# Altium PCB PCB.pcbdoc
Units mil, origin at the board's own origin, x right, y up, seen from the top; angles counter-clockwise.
Board outline 2605 x 3135 mil, 2 copper layers (Top Layer, Bottom Layer); 0 components, 0 nets, 4 pads, 4 vias.
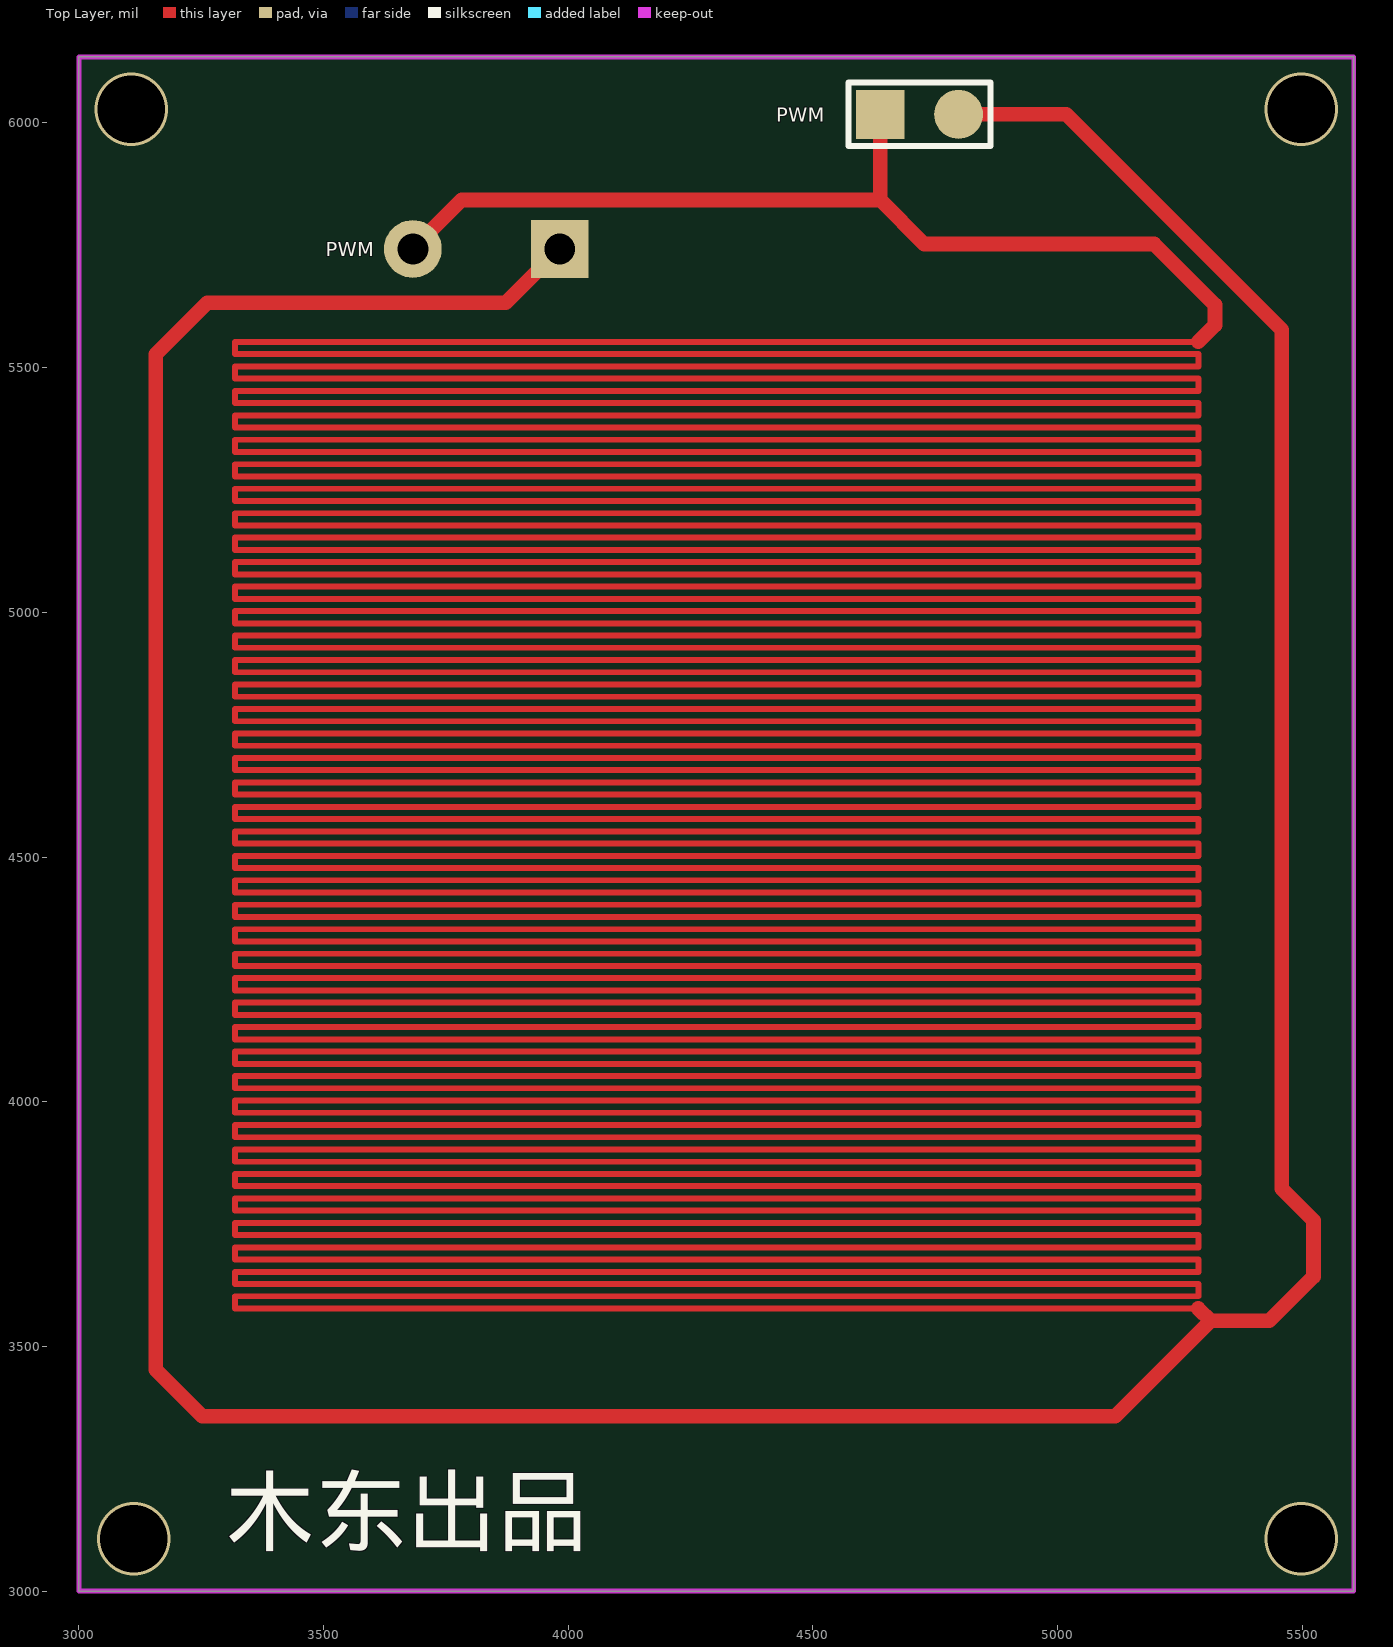
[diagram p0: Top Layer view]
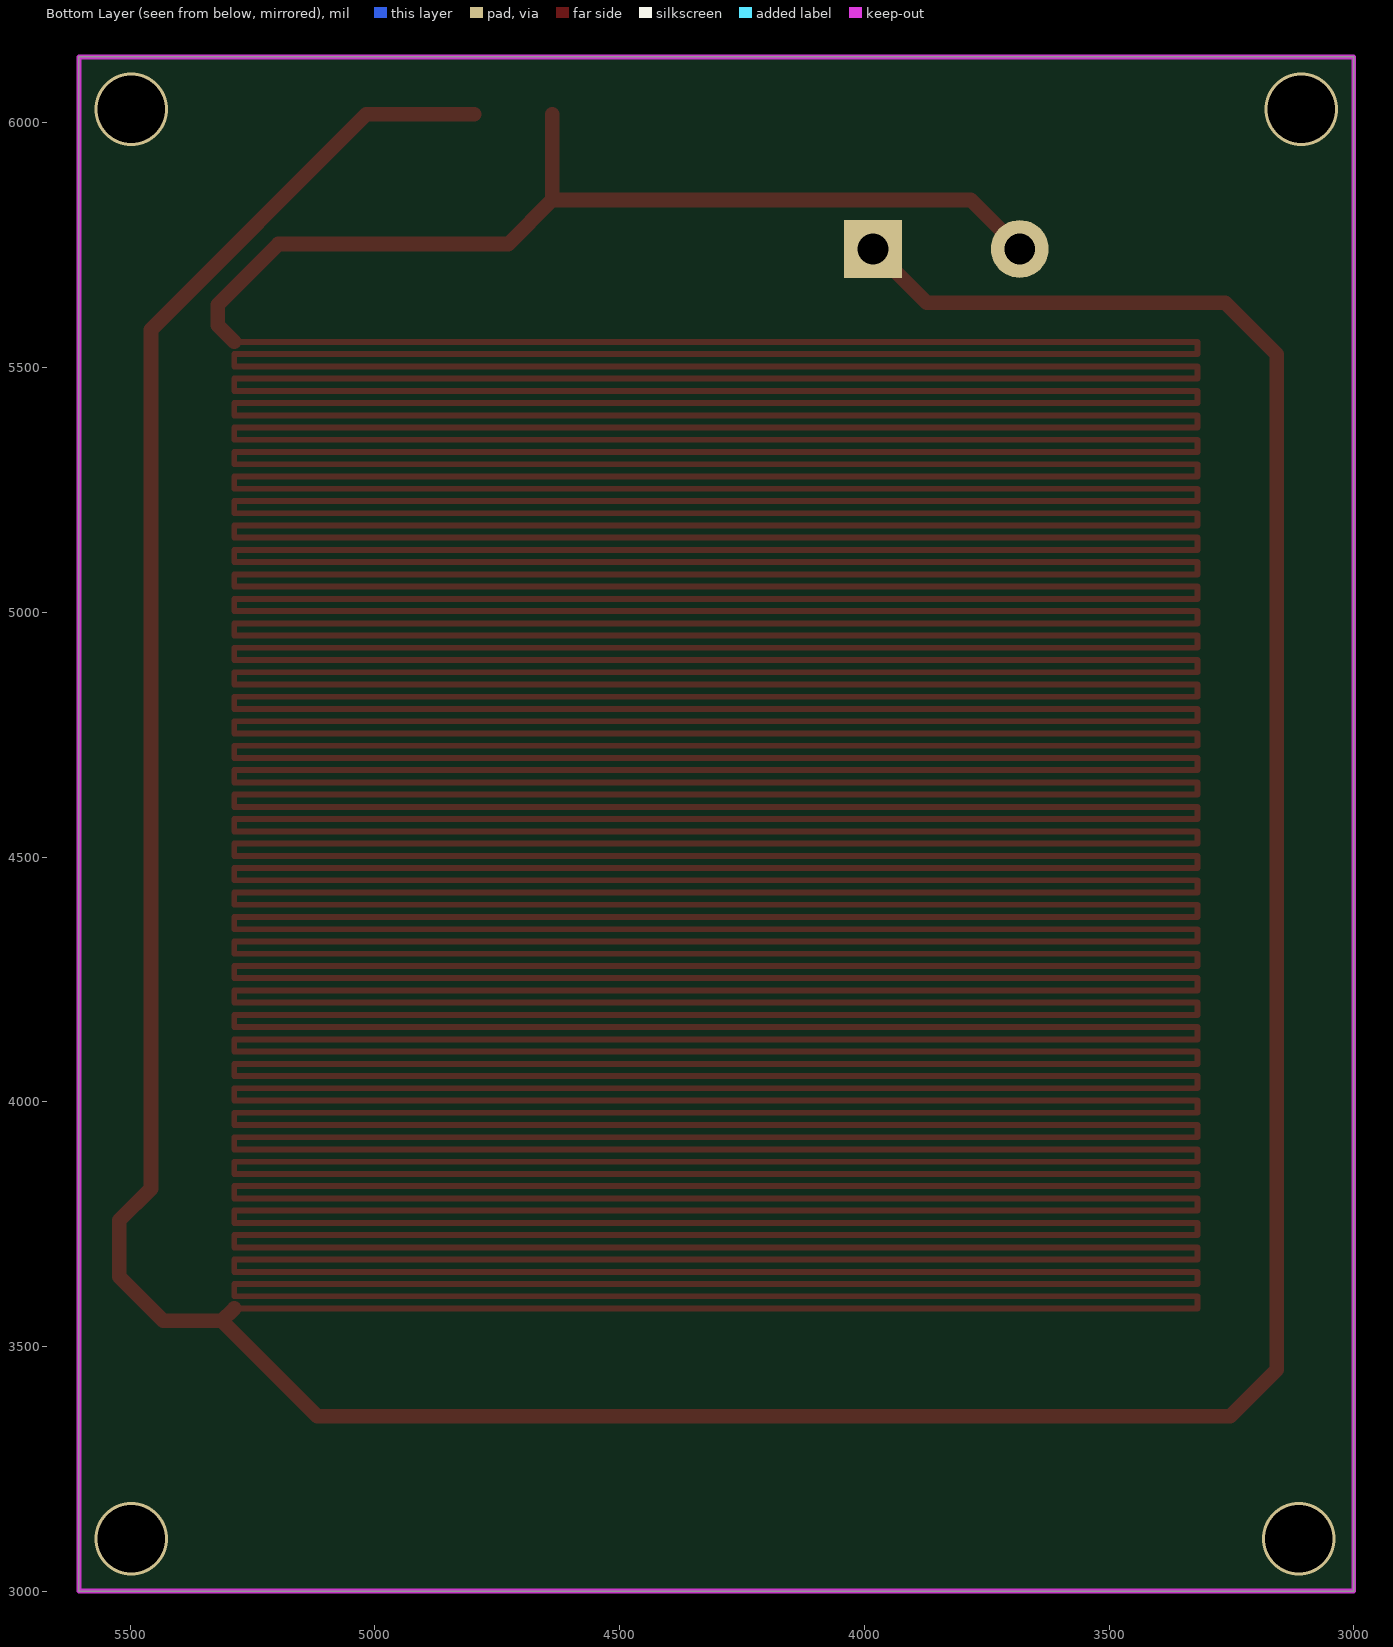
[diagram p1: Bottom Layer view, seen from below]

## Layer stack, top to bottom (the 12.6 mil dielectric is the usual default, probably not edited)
Top Layer: signal copper (thickness not stored)
Dielectric: dielectric 12.6, FR-4, Dk 4.8
Bottom Layer: signal copper (thickness not stored)

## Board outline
3000,3000 5605,3000 5605,6135 3000,6135

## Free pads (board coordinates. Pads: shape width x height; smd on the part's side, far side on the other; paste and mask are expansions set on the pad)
  rect 118.1x118.1 hole 63: GND(3982.5,5742.51)
  round 100 smd: GND(4797.5,6017.5)
  round 118.1 hole 63: PWM(3682.5,5742.5)
  rect 100x100 smd: PWM(4637.5,6017.5)

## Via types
v1: diameter 150, hole 137.8, Top Layer to Bottom Layer, 4 vias

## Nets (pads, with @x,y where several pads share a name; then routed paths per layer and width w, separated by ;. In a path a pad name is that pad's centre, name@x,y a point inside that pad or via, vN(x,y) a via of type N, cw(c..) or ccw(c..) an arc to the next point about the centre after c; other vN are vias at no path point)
copper on no net: | length 169840
  Top Layer w12: 5287.5,3577.5 3319,3577.5 3319,3602.5 5287.5,3602.5 5287.5,3627.5 3319,3627.5 3319,3652.5 5287.5,3652.5 5287.5,3677.5 3319,3677.5 3319,3702.5 5287.5,3702.5 5287.5,3727.5 3319,3727.5 3319,3752.5 5287.5,3752.5 5287.5,3777.5 3319,3777.5 3319,3802.5 5287.5,3802.5 5287.5,3827.5 3319,3827.5 3319,3852.5 5287.5,3852.5 5287.5,3877.5 3319,3877.5 3319,3902.5 5287.5,3902.5 5287.5,3927.5 3319,3927.5 3319,3952.5 5287.5,3952.5 5287.5,3977.5 3319,3977.5 3319,4002.5 5287.5,4002.5 5287.5,4027.5 3319,4027.5 3319,4052.5 5287.5,4052.5 5287.5,4077.5 3319,4077.5 3319,4102.5 5287.5,4102.5 5287.5,4127.5 3319,4127.5 3319,4152.5 5287.5,4152.5 5287.5,4177.5 3319,4177.5 3319,4202.5 5287.5,4202.5 5287.5,4227.5 3319,4227.5 3319,4252.5 5287.5,4252.5 5287.5,4277.5 3319,4277.5 3319,4302.5 5287.5,4302.5 5287.5,4327.5 3319,4327.5 3319,4352.5 5287.5,4352.5 5287.5,4377.5 3319,4377.5 3319,4402.5 5287.5,4402.5 5287.5,4427.5 3319,4427.5 3319,4452.5 5287.5,4452.5 5287.5,4477.5 3319,4477.5 3319,4502.5 5287.5,4502.5 5287.5,4527.5 3319,4527.5 3319,4552.5 5287.5,4552.5 5287.5,4577.5 3319,4577.5 3319,4602.5 5287.5,4602.5 5287.5,4627.5 3319,4627.5 3319,4652.5 5287.5,4652.5 5287.5,4677.5 3319,4677.5 3319,4702.5 5287.5,4702.5 5287.5,4727.5 3319,4727.5 3319,4752.5 5287.5,4752.5 5287.5,4777.5 3319,4777.5 3319,4802.5 5287.5,4802.5 5287.5,4827.5 3319,4827.5 3319,4852.5 5287.5,4852.5 5287.5,4877.5 3319,4877.5 3319,4902.5 5287.5,4902.5 5287.5,4927.5 3319,4927.5 3319,4952.5 5287.5,4952.5 5287.5,4977.5 3319,4977.5 3319,5002.5 5287.5,5002.5 5287.5,5027.5 3319,5027.5 3319,5052.5 5287.5,5052.5 5287.5,5077.5 3319,5077.5 3319,5102.5 5287.5,5102.5 5287.5,5127.5 3319,5127.5 3319,5152.5 5287.5,5152.5 5287.5,5177.5 3319,5177.5 3319,5202.5 5287.5,5202.5 5287.5,5227.5 3319,5227.5 3319,5252.5 5287.5,5252.5 5287.5,5277.5 3319,5277.5 3319,5302.5 5287.5,5302.5 5287.5,5327.5 3319,5327.5 3319,5352.5 5287.5,5352.5 5287.5,5377.5 3319,5377.5 3319,5402.5 5287.5,5402.5 5287.5,5427.5 3319,5427.5 3319,5452.5 5287.5,5452.5 5287.5,5477.5 3319,5477.5 3319,5502.5 5287.5,5502.5 5287.5,5527.5 3319,5527.5 3319,5552.5 5287.5,5552.5
  Top Layer w30: 3682.5,5742.5 3782.5,5842.5 4637.5,5842.5 ; 3982.5,5742.51 3872.49,5632.5 3262.5,5632.5 3157.5,5527.5 3157.5,3452.5 3252.5,3357.5 5117.5,3357.5 5312.5,3552.5 ; 4637.5,6017.5 4637.5,5842.5 ; 4797.5,6017.5 5017.5,6017.5 5457.5,5577.5 5457.5,3822.5 5522.5,3757.5 5522.5,3642.5 5432.5,3552.5 5312.5,3552.5 ; 5287.5,3577.5 5312.5,3552.5 ; 5287.5,5552.5 5321.29,5586.29 5321.29,5628.71 5197.5,5752.5 4727.5,5752.5 4637.5,5842.5
  other v1: 3112.5,3107.5 5497.5,3107.5 3107.5,6027.5 5497.5,6027.5

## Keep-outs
Board Outline Layer:
  the board outline again, w10

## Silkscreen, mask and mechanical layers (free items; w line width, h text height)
Top Silkscreen Layer:
  lines w12: 4572.5,5952.5 4862.5,5952.5 4862.5,6082.5 4572.5,6082.5 4572.5,5952.5
  text "PWM" at 4425.01,6002.49 h29.2
  text "PWM" at 3505.01,5727.49 h29.2
  text "木东出品" at 3297.99,3097.58 h135.94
